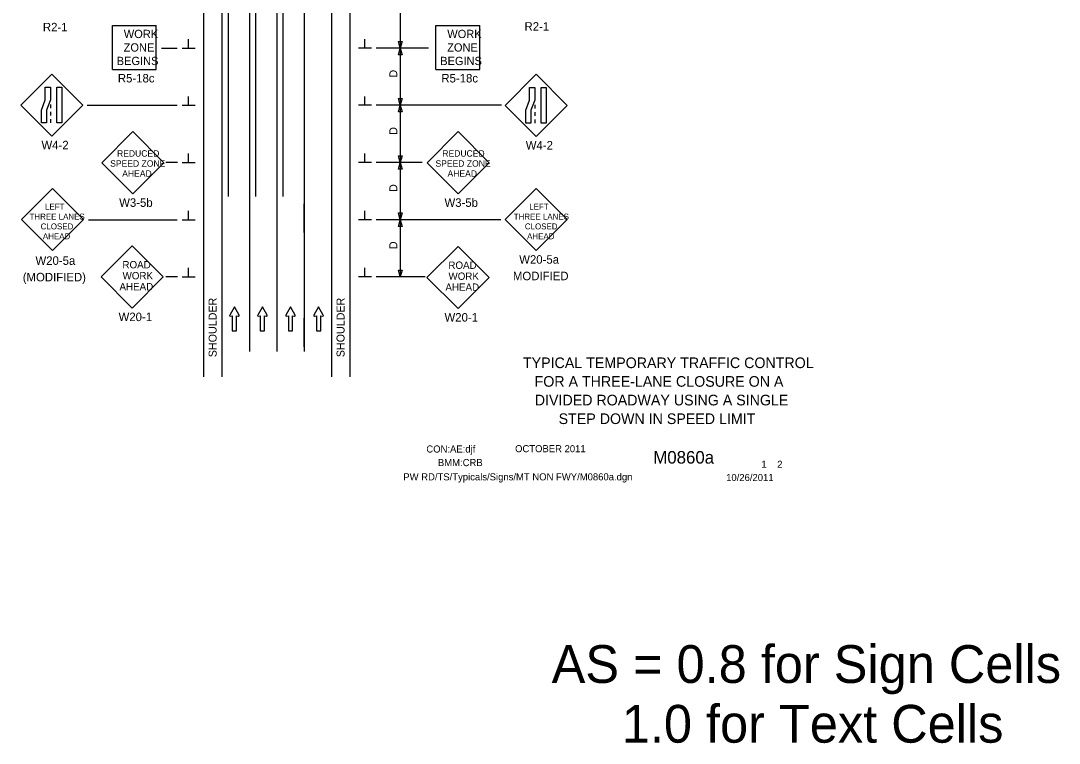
# Model space of a CAD drawing. Extents: x 16734 to 18475, y 5704 to 7011.
# Drawn here: x 16736 to 17644, y 5704 to 6336 of the extents above; entities that cross this region are included whole.
import ezdxf

# ---------------------------------------------------------------- set-up
doc = ezdxf.new("R2010")
doc.units = 0
for name, color, linetype in [('ALI_LEGAL_EX', 7, 'Continuous'), ('BORDER', 7, 'Continuous'), ('BORDER_SIGNAL_WO', 7, 'Continuous'), ('Level 3', 7, 'Continuous'), ('MT_SCRATCH_LEVEL_E', 7, 'Continuous'), ('PAVT_EDGE_EX', 7, 'Continuous'), ('TRAFFIC_SIGNS_PR', 7, 'Continuous'), ('TYPICAL_TEXT_DIMEN_PR', 7, 'Continuous')]:
    doc.layers.add(name, color=color, linetype=linetype)

msp = doc.modelspace()

# ---------------------------------------------------------------- linework, layer by layer
at = {"layer": 'ALI_LEGAL_EX'}
for p, q in [((16917.23, 7011.11), (16917.23, 6181.92)), ((16941.23, 7011.11), (16941.23, 6181.92)), ((16965.23, 7011.11), (16965.23, 6181.92)), ((16965.23, 7011.11), (16965.23, 6181.92)), ((16935.85, 6875.49), (16935.85, 6046.3)), ((16959.85, 6875.49), (16959.85, 6046.3)), ((16983.85, 6875.49), (16983.85, 6046.3)), ((16983.85, 6875.49), (16983.85, 6046.3))]:
    msp.add_line(p, q, dxfattribs=at)
for points in [[(16935.85, 6275.49), (16935.85, 6250.49)], [(16959.85, 6275.49), (16959.85, 6250.49)], [(16983.85, 6275.49), (16983.85, 6250.49)], [(16935.85, 6175.49), (16935.85, 6150.49)], [(16959.85, 6175.49), (16959.85, 6150.49)], [(16983.85, 6150.49), (16983.85, 6175.49)], [(16983.85, 6175.49), (16983.85, 6150.49)], [(16935.85, 6075.48), (16935.85, 6050.48)], [(16959.85, 6075.48), (16959.85, 6050.48)], [(16983.85, 6050.48), (16983.85, 6075.48)], [(16983.85, 6075.48), (16983.85, 6050.48)]]:
    msp.add_lwpolyline(points, dxfattribs=at)
at = {"layer": 'Level 3'}
for p, q in [((16873.1, 6211.65), (16862.81, 6211.65)), ((16873.1, 6111.65), (16862.81, 6111.65))]:
    msp.add_line(p, q, dxfattribs=at)
at = {"layer": 'MT_SCRATCH_LEVEL_E'}
for p, q in [((16922.76, 6085.3), (16918.65, 6078.06)), ((16922.76, 6085.3), (16918.65, 6078.06)), ((16919.14, 6077.38), (16920.91, 6077.69)), ((16919.14, 6077.38), (16920.91, 6077.69)), ((16920.91, 6077.69), (16920.91, 6064.44)), ((16920.91, 6077.69), (16920.91, 6064.44)), ((16926.91, 6078.06), (16922.76, 6085.3)), ((16926.91, 6078.06), (16922.76, 6085.3)), ((16924.65, 6064.44), (16924.65, 6077.69)), ((16924.65, 6077.69), (16926.43, 6077.38)), ((16924.65, 6064.44), (16924.65, 6077.69)), ((16924.65, 6077.69), (16926.43, 6077.38)), ((16947.29, 6085.3), (16943.18, 6078.06)), ((16947.29, 6085.3), (16943.18, 6078.06)), ((16943.67, 6077.38), (16945.44, 6077.69)), ((16943.67, 6077.38), (16945.44, 6077.69)), ((16945.44, 6077.69), (16945.44, 6064.44)), ((16945.44, 6077.69), (16945.44, 6064.44)), ((16951.44, 6078.06), (16947.29, 6085.3)), ((16951.44, 6078.06), (16947.29, 6085.3)), ((16949.18, 6064.44), (16949.18, 6077.69)), ((16949.18, 6077.69), (16950.96, 6077.38)), ((16949.18, 6064.44), (16949.18, 6077.69)), ((16949.18, 6077.69), (16950.96, 6077.38)), ((16971.82, 6085.3), (16967.71, 6078.06)), ((16971.82, 6085.3), (16967.71, 6078.06)), ((16968.19, 6077.38), (16969.97, 6077.69)), ((16968.19, 6077.38), (16969.97, 6077.69)), ((16969.97, 6077.69), (16969.97, 6064.44)), ((16969.97, 6077.69), (16969.97, 6064.44)), ((16975.97, 6078.06), (16971.82, 6085.3)), ((16975.97, 6078.06), (16971.82, 6085.3)), ((16973.71, 6064.44), (16973.71, 6077.69)), ((16973.71, 6077.69), (16975.49, 6077.38)), ((16973.71, 6064.44), (16973.71, 6077.69)), ((16973.71, 6077.69), (16975.49, 6077.38)), ((16996.38, 6085.3), (16992.27, 6078.06)), ((16996.38, 6085.3), (16992.27, 6078.06)), ((16992.75, 6077.38), (16994.53, 6077.69)), ((16992.75, 6077.38), (16994.53, 6077.69)), ((16994.53, 6077.69), (16994.53, 6064.44)), ((16994.53, 6077.69), (16994.53, 6064.44)), ((17000.53, 6078.06), (16996.38, 6085.3)), ((17000.53, 6078.06), (16996.38, 6085.3)), ((16998.27, 6064.44), (16998.27, 6077.69)), ((16998.27, 6077.69), (17000.05, 6077.38)), ((16998.27, 6064.44), (16998.27, 6077.69)), ((16998.27, 6077.69), (17000.05, 6077.38)), ((16920.91, 6064.44), (16924.65, 6064.44)), ((16920.91, 6064.44), (16924.65, 6064.44)), ((16945.44, 6064.44), (16949.18, 6064.44)), ((16945.44, 6064.44), (16949.18, 6064.44)), ((16969.97, 6064.44), (16973.71, 6064.44)), ((16969.97, 6064.44), (16973.71, 6064.44)), ((16994.53, 6064.44), (16998.27, 6064.44)), ((16994.53, 6064.44), (16998.27, 6064.44))]:
    msp.add_line(p, q, dxfattribs=at)
for centre, start, end in [((16919.06, 6077.84), 150.42484, 279.96381), ((16919.06, 6077.84), 150.42484, 279.96381), ((16926.5, 6077.84), 260.03619, 29.77312), ((16926.5, 6077.84), 260.03619, 29.77312), ((16943.59, 6077.84), 150.42484, 279.96381), ((16943.59, 6077.84), 150.42484, 279.96381), ((16951.03, 6077.84), 260.03619, 29.77312), ((16951.03, 6077.84), 260.03619, 29.77312), ((16968.12, 6077.84), 150.42484, 279.96381), ((16968.12, 6077.84), 150.42484, 279.96381), ((16975.56, 6077.84), 260.03619, 29.77312), ((16975.56, 6077.84), 260.03619, 29.77312), ((16992.68, 6077.84), 150.42484, 279.96381), ((16992.68, 6077.84), 150.42484, 279.96381), ((17000.12, 6077.84), 260.03619, 29.77312), ((17000.12, 6077.84), 260.03619, 29.77312)]:
    msp.add_arc(centre, 0.463, start, end, dxfattribs=at)
at = {"layer": 'PAVT_EDGE_EX'}
for p, q in [((16911.85, 6920.73), (16911.85, 6024.13)), ((17007.85, 6920.73), (17007.85, 6024.13)), ((17023.85, 6920.73), (17023.85, 6024.13)), ((16895.85, 6869.12), (16895.85, 6024.13))]:
    msp.add_line(p, q, dxfattribs=at)
at = {"layer": 'TRAFFIC_SIGNS_PR'}
for p, q in [((16816.04, 6293.05), (16816.04, 6331.45)), ((16816.04, 6331.45), (16854.44, 6331.45)), ((16854.44, 6293.05), (16854.44, 6331.45)), ((17099.01, 6293.05), (17099.01, 6331.45)), ((17099.01, 6331.45), (17137.41, 6331.45)), ((17137.41, 6293.05), (17137.41, 6331.45)), ((16763.06, 6288.91), (16735.91, 6261.76)), ((16790.21, 6261.76), (16763.06, 6288.91)), ((16816.04, 6293.05), (16854.44, 6293.05)), ((17099.01, 6293.05), (17137.41, 6293.05)), ((17186.69, 6288.74), (17159.54, 6261.59)), ((17213.85, 6261.59), (17186.69, 6288.74)), ((16735.91, 6261.76), (16763.06, 6234.6)), ((16761.81, 6262.25), (16761.81, 6259.05)), ((16763.06, 6234.6), (16790.21, 6261.76)), ((17159.54, 6261.59), (17186.69, 6234.43)), ((17185.45, 6262.08), (17185.45, 6258.88)), ((17186.69, 6234.43), (17213.85, 6261.59)), ((16761.81, 6255.85), (16761.81, 6252.65)), ((17185.45, 6255.68), (17185.45, 6252.48)), ((16761.81, 6249.45), (16761.81, 6246.25)), ((17185.45, 6249.28), (17185.45, 6246.08)), ((16834.04, 6238.6), (16806.89, 6211.45)), ((16861.19, 6211.45), (16834.04, 6238.6)), ((17118.6, 6238.6), (17091.45, 6211.45)), ((17145.76, 6211.45), (17118.6, 6238.6)), ((16806.89, 6211.45), (16834.04, 6184.3)), ((16834.04, 6184.3), (16861.19, 6211.45)), ((17091.45, 6211.45), (17118.6, 6184.3)), ((17118.6, 6184.3), (17145.76, 6211.45)), ((16763.65, 6188.88), (16736.49, 6161.73)), ((16790.8, 6161.73), (16763.65, 6188.88)), ((17186.78, 6188.88), (17159.63, 6161.73)), ((17213.93, 6161.73), (17186.78, 6188.88)), ((16736.49, 6161.73), (16763.65, 6134.58)), ((16763.65, 6134.58), (16790.8, 6161.73)), ((17159.63, 6161.73), (17186.78, 6134.58)), ((17186.78, 6134.58), (17213.93, 6161.73)), ((16833.31, 6138.7), (16806.16, 6111.54)), ((16860.46, 6111.54), (16833.31, 6138.7)), ((17118.4, 6138.28), (17091.25, 6111.12)), ((17145.56, 6111.12), (17118.4, 6138.28)), ((16806.16, 6111.54), (16833.31, 6084.39)), ((16833.31, 6084.39), (16860.46, 6111.54)), ((17091.25, 6111.12), (17118.4, 6083.97)), ((17118.4, 6083.97), (17145.56, 6111.12))]:
    msp.add_line(p, q, dxfattribs=at)
for points in [[(16761.81, 6277.49), (16761.81, 6266.31), (16758.47, 6257.43), (16758.47, 6246.25), (16753.98, 6246.25), (16753.98, 6257.43), (16757.32, 6266.31), (16757.32, 6277.49)], [(16771.95, 6277.49), (16771.95, 6246.25), (16767.46, 6246.25), (16767.46, 6277.49)], [(17185.45, 6277.32), (17185.45, 6266.14), (17182.1, 6257.26), (17182.1, 6246.08), (17177.61, 6246.08), (17177.61, 6257.26), (17180.95, 6266.14), (17180.95, 6277.32)], [(17195.58, 6277.32), (17195.58, 6246.08), (17191.09, 6246.08), (17191.09, 6277.32)]]:
    msp.add_lwpolyline(points, close=True, dxfattribs=at)
at = {"layer": 'TYPICAL_TEXT_DIMEN_PR'}
for p, q in [((17067.85, 6361.65), (17067.85, 6311.65)), ((16882.73, 6311.65), (16882.73, 6319.43)), ((17036.98, 6311.65), (17036.98, 6319.43)), ((17067.85, 6311.65), (17066.28, 6317.51)), ((17066.28, 6317.51), (17067.85, 6317.51)), ((17067.85, 6317.51), (17069.42, 6317.51)), ((17069.42, 6317.51), (17067.85, 6311.65)), ((16858.94, 6311.65), (16872.85, 6311.65)), ((16877.1, 6311.65), (16888.35, 6311.65)), ((17042.6, 6311.65), (17031.35, 6311.65)), ((17092.67, 6311.65), (17046.85, 6311.65)), ((17066.28, 6305.79), (17067.85, 6311.65)), ((17067.85, 6305.79), (17066.28, 6305.79)), ((17067.85, 6311.65), (17069.42, 6305.79)), ((17067.85, 6311.65), (17067.85, 6261.65)), ((17069.42, 6305.79), (17067.85, 6305.79)), ((16882.73, 6261.65), (16882.73, 6269.43)), ((17036.98, 6261.65), (17036.98, 6269.43)), ((16794.03, 6261.65), (16872.85, 6261.65)), ((16877.1, 6261.65), (16888.35, 6261.65)), ((17042.6, 6261.65), (17031.35, 6261.65)), ((17156.47, 6261.65), (17046.85, 6261.65)), ((17067.85, 6261.65), (17066.28, 6267.51)), ((17066.28, 6267.51), (17067.85, 6267.51)), ((17066.28, 6255.79), (17067.85, 6261.65)), ((17067.85, 6267.51), (17069.42, 6267.51)), ((17069.42, 6267.51), (17067.85, 6261.65)), ((17067.85, 6261.65), (17067.85, 6211.65)), ((17067.85, 6261.65), (17069.42, 6255.79)), ((17067.85, 6255.79), (17066.28, 6255.79)), ((17069.42, 6255.79), (17067.85, 6255.79)), ((16882.73, 6211.65), (16882.73, 6219.43)), ((17036.98, 6211.65), (17036.98, 6219.43)), ((17067.85, 6211.65), (17066.28, 6217.51)), ((17066.28, 6217.51), (17067.85, 6217.51)), ((17067.85, 6217.51), (17069.42, 6217.51)), ((17069.42, 6217.51), (17067.85, 6211.65)), ((16877.1, 6211.65), (16888.35, 6211.65)), ((17042.6, 6211.65), (17031.35, 6211.65)), ((17087.07, 6211.65), (17046.85, 6211.65)), ((17066.28, 6205.79), (17067.85, 6211.65)), ((17067.85, 6205.79), (17066.28, 6205.79)), ((17067.85, 6211.65), (17067.85, 6161.65)), ((17067.85, 6211.65), (17069.42, 6205.79)), ((17069.42, 6205.79), (17067.85, 6205.79)), ((16882.73, 6161.65), (16882.73, 6169.43)), ((17036.98, 6161.65), (17036.98, 6169.43)), ((16795.03, 6161.65), (16872.85, 6161.65)), ((16877.1, 6161.65), (16888.35, 6161.65)), ((17042.6, 6161.65), (17031.35, 6161.65)), ((17155.93, 6161.65), (17046.85, 6161.65)), ((17067.85, 6161.65), (17066.28, 6167.51)), ((17066.28, 6167.51), (17067.85, 6167.51)), ((17066.28, 6155.79), (17067.85, 6161.65)), ((17067.85, 6167.51), (17069.42, 6167.51)), ((17069.42, 6167.51), (17067.85, 6161.65)), ((17067.85, 6161.65), (17067.85, 6111.65)), ((17067.85, 6161.65), (17069.42, 6155.79)), ((17067.85, 6155.79), (17066.28, 6155.79)), ((17069.42, 6155.79), (17067.85, 6155.79)), ((16882.73, 6111.65), (16882.73, 6119.43)), ((17036.98, 6111.65), (17036.98, 6119.43)), ((17067.85, 6111.65), (17066.28, 6117.51)), ((17066.28, 6117.51), (17067.85, 6117.51)), ((17067.85, 6117.51), (17069.42, 6117.51)), ((17069.42, 6117.51), (17067.85, 6111.65)), ((16877.1, 6111.65), (16888.35, 6111.65)), ((17042.6, 6111.65), (17031.35, 6111.65)), ((17089.74, 6111.65), (17046.85, 6111.65))]:
    msp.add_line(p, q, dxfattribs=at)

# ---------------------------------------------------------------- texts
at = {"layer": 'BORDER'}
for s, p in [('TYPICAL TEMPORARY TRAFFIC CONTROL', (17175.21, 6031.88)), (' FOR A THREE-LANE CLOSURE ON A ', (17181.92, 6015.58)), ('DIVIDED ROADWAY USING A SINGLE', (17185.56, 5999.28)), ('STEP DOWN IN SPEED LIMIT', (17206.42, 5982.98))]:
    msp.add_text(s, height=9.3, dxfattribs=at).set_placement(p)
at = {"layer": 'BORDER_SIGNAL_WO'}
for s, height, p in [('CON:AE:djf', 6.2, (17090.69, 5958.06)), ('    OCTOBER 2011    ', 6.2, (17159.08, 5958.34)), ('    M0860a   ', 11, (17272.86, 5948.38)), ('BMM:CRB   ', 6.2, (17100.81, 5946.17)), (' 1    2 ', 6.2, (17381.45, 5944.7)), (' 1    2 ', 6.2, (17381.45, 5944.7)), ('PW RD/TS/Typicals/Signs/MT NON FWY/M0860a.dgn    ', 6.2, (17070.55, 5933.71)), ('10/26/2011    ', 6.2, (17352.93, 5933.13)), ('AS = 0.8 for Sign Cells', 33.0301, (17200.31, 5756.64)), ('     1.0 for Text Cells', 33.0301, (17200.31, 5704.41))]:
    msp.add_text(s, height=height, dxfattribs=at).set_placement(p)
at = {"layer": 'TRAFFIC_SIGNS_PR'}
for s, height, p in [('R2-1', 7.44, (16755.26, 6326.28)), ('R2-1', 7.44, (17176.56, 6326.86)), ('WORK', 7.217, (16826.04, 6320.42)), ('WORK', 7.217, (17109.01, 6320.42)), ('ZONE', 7.217, (16825.92, 6308.61)), ('ZONE', 7.217, (17108.9, 6308.61)), ('BEGINS', 7.217, (16819.85, 6296.8)), ('BEGINS', 7.217, (17102.82, 6296.8)), ('R5-18c', 7.44, (16820.85, 6281.61)), ('R5-18c', 7.44, (17103.83, 6281.61)), ('W4-2', 7.44, (16754.02, 6223.16)), ('W4-2', 7.44, (17177.65, 6222.99)), ('SPEED ZONE', 5.6, (16814.09, 6207.96)), ('REDUCED', 5.6, (16820.1, 6216.76)), ('SPEED ZONE', 5.6, (17098.65, 6207.96)), ('REDUCED', 5.6, (17104.66, 6216.76)), ('AHEAD', 5.6, (16824.65, 6199.16)), ('AHEAD', 5.6, (17109.21, 6199.16)), ('W3-5b', 7.44, (16821.99, 6172.86)), ('W3-5b', 7.44, (17106.56, 6172.86)), ('LEFT', 5.2, (16757.12, 6170.35)), ('LEFT', 5.2, (17180.69, 6170.35)), ('THREE LANES', 5.2, (16743.57, 6161.75)), ('THREE LANES', 5.2, (17167.14, 6161.75)), ('CLOSED', 5.2, (16753.3, 6153.15)), ('CLOSED', 5.2, (17176.87, 6153.15)), ('AHEAD', 5.2, (16755.24, 6144.55)), ('AHEAD', 5.2, (17178.81, 6144.55)), ('W20-5a', 7.44, (16748.79, 6122.14)), ('ROAD', 6.4, (16824.85, 6119.08)), ('ROAD', 6.4, (17109.95, 6118.66)), ('W20-5a', 7.44, (17171.92, 6123.14)), ('(MODIFIED)', 7.44, (16737.64, 6107.7)), ('WORK', 6.4, (16824.96, 6109.48)), ('WORK', 6.4, (17110.06, 6109.06)), ('MODIFIED', 7.44, (17166.43, 6108.7)), ('AHEAD', 6.4, (16822.27, 6099.88)), ('AHEAD', 6.4, (17107.37, 6099.46)), ('W20-1', 7.44, (16821.48, 6072.95)), ('W20-1', 7.44, (17106.57, 6072.53))]:
    msp.add_text(s, height=height, dxfattribs=at).set_placement(p)
at = {"layer": 'TYPICAL_TEXT_DIMEN_PR'}
for s, p in [('D', (17065.3, 6285.87)), ('D', (17065.3, 6235.87)), ('D', (17065.3, 6185.87)), ('D', (17065.3, 6135.87)), ('SHOULDER', (16907.23, 6041.41)), ('SHOULDER', (17019.14, 6041.41))]:
    msp.add_text(s, height=7, rotation=90, dxfattribs=at).set_placement(p)

doc.saveas('drawing.dxf')
